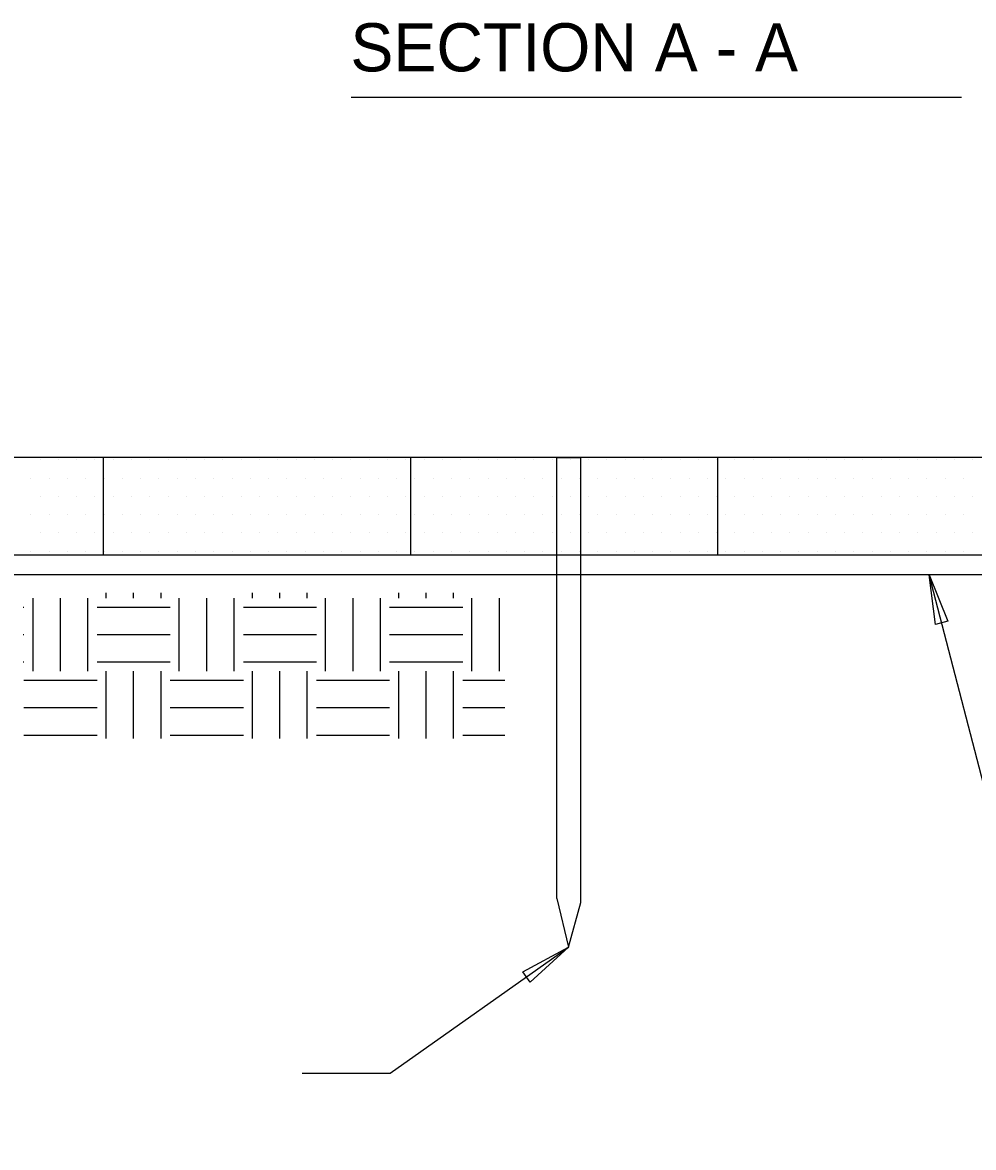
# Model space of a CAD drawing. Extents: x 638850 to 644908, y 297188 to 298900.
# Drawn here: x 641700.1 to 641771.2, y 297633.7 to 297717.8 of the extents above; entities that cross this region are included whole.
import ezdxf

# ---------------------------------------------------------------- set-up
doc = ezdxf.new("R2010")
doc.units = 0
for name, color, linetype in [('11', 7, 'Continuous'), ('12', 7, 'Continuous'), ('3', 7, 'Continuous'), ('4', 7, 'Continuous'), ('5', 7, 'Continuous'), ('6', 7, 'Continuous'), ('7', 7, 'Continuous')]:
    doc.layers.add(name, color=color, linetype=linetype)

msp = doc.modelspace()

# ---------------------------------------------------------------- linework, layer by layer
at = {"layer": '11'}
for p, q in [((641701.416, 297685.127), (641701.416, 297685.127)), ((641702.783, 297685.127), (641702.783, 297685.127)), ((641704.15, 297685.127), (641704.15, 297685.127)), ((641705.517, 297685.127), (641705.517, 297685.127)), ((641706.883, 297685.127), (641706.883, 297685.127)), ((641708.25, 297685.127), (641708.25, 297685.127)), ((641709.617, 297685.127), (641709.617, 297685.127)), ((641710.984, 297685.127), (641710.984, 297685.127)), ((641712.351, 297685.127), (641712.351, 297685.127)), ((641713.718, 297685.127), (641713.718, 297685.127)), ((641715.085, 297685.127), (641715.085, 297685.127)), ((641716.452, 297685.127), (641716.452, 297685.127)), ((641717.818, 297685.127), (641717.818, 297685.127)), ((641719.185, 297685.127), (641719.185, 297685.127)), ((641720.552, 297685.127), (641720.552, 297685.127)), ((641721.919, 297685.127), (641721.919, 297685.127)), ((641723.286, 297685.127), (641723.286, 297685.127)), ((641724.653, 297685.127), (641724.653, 297685.127)), ((641726.02, 297685.127), (641726.02, 297685.127)), ((641727.387, 297685.127), (641727.387, 297685.127)), ((641728.753, 297685.127), (641728.753, 297685.127)), ((641730.12, 297685.127), (641730.12, 297685.127)), ((641731.487, 297685.127), (641731.487, 297685.127)), ((641732.854, 297685.127), (641732.854, 297685.127)), ((641734.221, 297685.127), (641734.221, 297685.127)), ((641735.588, 297685.127), (641735.588, 297685.127)), ((641736.955, 297685.127), (641736.955, 297685.127)), ((641738.322, 297685.127), (641738.322, 297685.127)), ((641739.688, 297685.127), (641739.688, 297685.127)), ((641741.055, 297685.127), (641741.055, 297685.127)), ((641742.422, 297685.127), (641742.422, 297685.127)), ((641743.789, 297685.127), (641743.789, 297685.127)), ((641745.156, 297685.127), (641745.156, 297685.127)), ((641746.523, 297685.127), (641746.523, 297685.127)), ((641747.89, 297685.127), (641747.89, 297685.127)), ((641749.257, 297685.127), (641749.257, 297685.127)), ((641750.623, 297685.127), (641750.623, 297685.127)), ((641751.99, 297685.127), (641751.99, 297685.127)), ((641753.357, 297685.127), (641753.357, 297685.127)), ((641754.724, 297685.127), (641754.724, 297685.127)), ((641756.091, 297685.127), (641756.091, 297685.127)), ((641757.458, 297685.127), (641757.458, 297685.127)), ((641758.825, 297685.127), (641758.825, 297685.127)), ((641760.192, 297685.127), (641760.192, 297685.127)), ((641761.558, 297685.127), (641761.558, 297685.127)), ((641762.925, 297685.127), (641762.925, 297685.127)), ((641764.292, 297685.127), (641764.292, 297685.127)), ((641765.659, 297685.127), (641765.659, 297685.127)), ((641767.026, 297685.127), (641767.026, 297685.127)), ((641768.393, 297685.127), (641768.393, 297685.127)), ((641769.76, 297685.127), (641769.76, 297685.127)), ((641771.127, 297685.127), (641771.127, 297685.127)), ((641700.731, 297683.76), (641700.731, 297683.76)), ((641702.1, 297683.76), (641702.1, 297683.76)), ((641703.465, 297683.76), (641703.465, 297683.76)), ((641704.834, 297683.76), (641704.834, 297683.76)), ((641706.199, 297683.76), (641706.199, 297683.76)), ((641707.568, 297683.76), (641707.568, 297683.76)), ((641708.933, 297683.76), (641708.933, 297683.76)), ((641710.302, 297683.76), (641710.302, 297683.76)), ((641711.666, 297683.76), (641711.666, 297683.76)), ((641713.035, 297683.76), (641713.035, 297683.76)), ((641714.4, 297683.76), (641714.4, 297683.76)), ((641715.769, 297683.76), (641715.769, 297683.76)), ((641717.134, 297683.76), (641717.134, 297683.76)), ((641718.503, 297683.76), (641718.503, 297683.76)), ((641719.868, 297683.76), (641719.868, 297683.76)), ((641721.237, 297683.76), (641721.237, 297683.76)), ((641722.601, 297683.76), (641722.601, 297683.76)), ((641723.97, 297683.76), (641723.97, 297683.76)), ((641725.335, 297683.76), (641725.335, 297683.76)), ((641726.704, 297683.76), (641726.704, 297683.76)), ((641728.069, 297683.76), (641728.069, 297683.76)), ((641729.438, 297683.76), (641729.438, 297683.76)), ((641730.803, 297683.76), (641730.803, 297683.76)), ((641732.172, 297683.76), (641732.172, 297683.76)), ((641733.536, 297683.76), (641733.536, 297683.76)), ((641734.905, 297683.76), (641734.905, 297683.76)), ((641736.27, 297683.76), (641736.27, 297683.76)), ((641737.639, 297683.76), (641737.639, 297683.76)), ((641739.004, 297683.76), (641739.004, 297683.76)), ((641740.373, 297683.76), (641740.373, 297683.76)), ((641741.738, 297683.76), (641741.738, 297683.76)), ((641743.107, 297683.76), (641743.107, 297683.76)), ((641744.471, 297683.76), (641744.471, 297683.76)), ((641745.84, 297683.76), (641745.84, 297683.76)), ((641747.205, 297683.76), (641747.205, 297683.76)), ((641748.574, 297683.76), (641748.574, 297683.76)), ((641749.939, 297683.76), (641749.939, 297683.76)), ((641751.308, 297683.76), (641751.308, 297683.76)), ((641752.673, 297683.76), (641752.673, 297683.76)), ((641754.042, 297683.76), (641754.042, 297683.76)), ((641755.406, 297683.76), (641755.406, 297683.76)), ((641756.775, 297683.76), (641756.775, 297683.76)), ((641758.14, 297683.76), (641758.14, 297683.76)), ((641759.509, 297683.76), (641759.509, 297683.76)), ((641760.874, 297683.76), (641760.874, 297683.76)), ((641762.243, 297683.76), (641762.243, 297683.76)), ((641763.608, 297683.76), (641763.608, 297683.76)), ((641764.977, 297683.76), (641764.977, 297683.76)), ((641766.341, 297683.76), (641766.341, 297683.76)), ((641767.71, 297683.76), (641767.71, 297683.76)), ((641769.075, 297683.76), (641769.075, 297683.76)), ((641770.444, 297683.76), (641770.444, 297683.76)), ((641701.416, 297682.393), (641701.416, 297682.393)), ((641702.783, 297682.393), (641702.783, 297682.393)), ((641704.15, 297682.393), (641704.15, 297682.393)), ((641705.517, 297682.393), (641705.517, 297682.393)), ((641706.883, 297682.393), (641706.883, 297682.393)), ((641708.25, 297682.393), (641708.25, 297682.393)), ((641709.617, 297682.393), (641709.617, 297682.393)), ((641710.984, 297682.393), (641710.984, 297682.393)), ((641712.351, 297682.393), (641712.351, 297682.393)), ((641713.718, 297682.393), (641713.718, 297682.393)), ((641715.085, 297682.393), (641715.085, 297682.393)), ((641716.452, 297682.393), (641716.452, 297682.393)), ((641717.818, 297682.393), (641717.818, 297682.393)), ((641719.185, 297682.393), (641719.185, 297682.393)), ((641720.552, 297682.393), (641720.552, 297682.393)), ((641721.919, 297682.393), (641721.919, 297682.393)), ((641723.286, 297682.393), (641723.286, 297682.393)), ((641724.653, 297682.393), (641724.653, 297682.393)), ((641726.02, 297682.393), (641726.02, 297682.393)), ((641727.387, 297682.393), (641727.387, 297682.393)), ((641728.753, 297682.393), (641728.753, 297682.393)), ((641730.12, 297682.393), (641730.12, 297682.393)), ((641731.487, 297682.393), (641731.487, 297682.393)), ((641732.854, 297682.393), (641732.854, 297682.393)), ((641734.221, 297682.393), (641734.221, 297682.393)), ((641735.588, 297682.393), (641735.588, 297682.393)), ((641736.955, 297682.393), (641736.955, 297682.393)), ((641738.322, 297682.393), (641738.322, 297682.393)), ((641739.688, 297682.393), (641739.688, 297682.393)), ((641741.055, 297682.393), (641741.055, 297682.393)), ((641742.422, 297682.393), (641742.422, 297682.393)), ((641743.789, 297682.393), (641743.789, 297682.393)), ((641745.156, 297682.393), (641745.156, 297682.393)), ((641746.523, 297682.393), (641746.523, 297682.393)), ((641747.89, 297682.393), (641747.89, 297682.393)), ((641749.257, 297682.393), (641749.257, 297682.393)), ((641750.623, 297682.393), (641750.623, 297682.393)), ((641751.99, 297682.393), (641751.99, 297682.393)), ((641753.357, 297682.393), (641753.357, 297682.393)), ((641754.724, 297682.393), (641754.724, 297682.393)), ((641756.091, 297682.393), (641756.091, 297682.393)), ((641757.458, 297682.393), (641757.458, 297682.393)), ((641758.825, 297682.393), (641758.825, 297682.393)), ((641760.192, 297682.393), (641760.192, 297682.393)), ((641761.558, 297682.393), (641761.558, 297682.393)), ((641762.925, 297682.393), (641762.925, 297682.393)), ((641764.292, 297682.393), (641764.292, 297682.393)), ((641765.659, 297682.393), (641765.659, 297682.393)), ((641767.026, 297682.393), (641767.026, 297682.393)), ((641768.393, 297682.393), (641768.393, 297682.393)), ((641769.76, 297682.393), (641769.76, 297682.393)), ((641771.127, 297682.393), (641771.127, 297682.393)), ((641700.731, 297681.026), (641700.731, 297681.026)), ((641702.1, 297681.026), (641702.1, 297681.026)), ((641703.465, 297681.026), (641703.465, 297681.026)), ((641704.834, 297681.026), (641704.834, 297681.026)), ((641706.199, 297681.026), (641706.199, 297681.026)), ((641707.568, 297681.026), (641707.568, 297681.026)), ((641708.933, 297681.026), (641708.933, 297681.026)), ((641710.302, 297681.026), (641710.302, 297681.026)), ((641711.666, 297681.026), (641711.666, 297681.026)), ((641713.035, 297681.026), (641713.035, 297681.026)), ((641714.4, 297681.026), (641714.4, 297681.026)), ((641715.769, 297681.026), (641715.769, 297681.026)), ((641717.134, 297681.026), (641717.134, 297681.026)), ((641718.503, 297681.026), (641718.503, 297681.026)), ((641719.868, 297681.026), (641719.868, 297681.026)), ((641721.237, 297681.026), (641721.237, 297681.026)), ((641722.601, 297681.026), (641722.601, 297681.026)), ((641723.97, 297681.026), (641723.97, 297681.026)), ((641725.335, 297681.026), (641725.335, 297681.026)), ((641726.704, 297681.026), (641726.704, 297681.026)), ((641728.069, 297681.026), (641728.069, 297681.026)), ((641729.438, 297681.026), (641729.438, 297681.026)), ((641730.803, 297681.026), (641730.803, 297681.026)), ((641732.172, 297681.026), (641732.172, 297681.026)), ((641733.536, 297681.026), (641733.536, 297681.026)), ((641734.905, 297681.026), (641734.905, 297681.026)), ((641736.27, 297681.026), (641736.27, 297681.026)), ((641737.639, 297681.026), (641737.639, 297681.026)), ((641739.004, 297681.026), (641739.004, 297681.026)), ((641740.373, 297681.026), (641740.373, 297681.026)), ((641741.738, 297681.026), (641741.738, 297681.026)), ((641743.107, 297681.026), (641743.107, 297681.026)), ((641744.471, 297681.026), (641744.471, 297681.026)), ((641745.84, 297681.026), (641745.84, 297681.026)), ((641747.205, 297681.026), (641747.205, 297681.026)), ((641748.574, 297681.026), (641748.574, 297681.026)), ((641749.939, 297681.026), (641749.939, 297681.026)), ((641751.308, 297681.026), (641751.308, 297681.026)), ((641752.673, 297681.026), (641752.673, 297681.026)), ((641754.042, 297681.026), (641754.042, 297681.026)), ((641755.406, 297681.026), (641755.406, 297681.026)), ((641756.775, 297681.026), (641756.775, 297681.026)), ((641758.14, 297681.026), (641758.14, 297681.026)), ((641759.509, 297681.026), (641759.509, 297681.026)), ((641760.874, 297681.026), (641760.874, 297681.026)), ((641762.243, 297681.026), (641762.243, 297681.026)), ((641763.608, 297681.026), (641763.608, 297681.026)), ((641764.977, 297681.026), (641764.977, 297681.026)), ((641766.341, 297681.026), (641766.341, 297681.026)), ((641767.71, 297681.026), (641767.71, 297681.026)), ((641769.075, 297681.026), (641769.075, 297681.026)), ((641770.444, 297681.026), (641770.444, 297681.026)), ((641701.416, 297679.659), (641701.416, 297679.659)), ((641702.783, 297679.659), (641702.783, 297679.659)), ((641704.15, 297679.659), (641704.15, 297679.659)), ((641705.517, 297679.659), (641705.517, 297679.659)), ((641706.883, 297679.659), (641706.883, 297679.659)), ((641708.25, 297679.659), (641708.25, 297679.659)), ((641709.617, 297679.659), (641709.617, 297679.659)), ((641710.984, 297679.659), (641710.984, 297679.659)), ((641712.351, 297679.659), (641712.351, 297679.659)), ((641713.718, 297679.659), (641713.718, 297679.659)), ((641715.085, 297679.659), (641715.085, 297679.659)), ((641716.452, 297679.659), (641716.452, 297679.659)), ((641717.818, 297679.659), (641717.818, 297679.659)), ((641719.185, 297679.659), (641719.185, 297679.659)), ((641720.552, 297679.659), (641720.552, 297679.659)), ((641721.919, 297679.659), (641721.919, 297679.659)), ((641723.286, 297679.659), (641723.286, 297679.659)), ((641724.653, 297679.659), (641724.653, 297679.659)), ((641726.02, 297679.659), (641726.02, 297679.659)), ((641727.387, 297679.659), (641727.387, 297679.659)), ((641728.753, 297679.659), (641728.753, 297679.659)), ((641730.12, 297679.659), (641730.12, 297679.659)), ((641731.487, 297679.659), (641731.487, 297679.659)), ((641732.854, 297679.659), (641732.854, 297679.659)), ((641734.221, 297679.659), (641734.221, 297679.659)), ((641735.588, 297679.659), (641735.588, 297679.659)), ((641736.955, 297679.659), (641736.955, 297679.659)), ((641738.322, 297679.659), (641738.322, 297679.659)), ((641739.688, 297679.659), (641739.688, 297679.659)), ((641741.055, 297679.659), (641741.055, 297679.659)), ((641742.422, 297679.659), (641742.422, 297679.659)), ((641743.789, 297679.659), (641743.789, 297679.659)), ((641745.156, 297679.659), (641745.156, 297679.659)), ((641746.523, 297679.659), (641746.523, 297679.659)), ((641747.89, 297679.659), (641747.89, 297679.659)), ((641749.257, 297679.659), (641749.257, 297679.659)), ((641750.623, 297679.659), (641750.623, 297679.659)), ((641751.99, 297679.659), (641751.99, 297679.659)), ((641753.357, 297679.659), (641753.357, 297679.659)), ((641754.724, 297679.659), (641754.724, 297679.659)), ((641756.091, 297679.659), (641756.091, 297679.659)), ((641757.458, 297679.659), (641757.458, 297679.659)), ((641758.825, 297679.659), (641758.825, 297679.659)), ((641760.192, 297679.659), (641760.192, 297679.659)), ((641761.558, 297679.659), (641761.558, 297679.659)), ((641762.925, 297679.659), (641762.925, 297679.659)), ((641764.292, 297679.659), (641764.292, 297679.659)), ((641765.659, 297679.659), (641765.659, 297679.659)), ((641767.026, 297679.659), (641767.026, 297679.659)), ((641768.393, 297679.659), (641768.393, 297679.659)), ((641769.76, 297679.659), (641769.76, 297679.659)), ((641771.127, 297679.659), (641771.127, 297679.659)), ((641700.731, 297678.292), (641700.731, 297678.292)), ((641702.1, 297678.292), (641702.1, 297678.292)), ((641703.465, 297678.292), (641703.465, 297678.292)), ((641704.834, 297678.292), (641704.834, 297678.292)), ((641706.199, 297678.292), (641706.199, 297678.292)), ((641707.568, 297678.292), (641707.568, 297678.292)), ((641708.933, 297678.292), (641708.933, 297678.292)), ((641710.302, 297678.292), (641710.302, 297678.292)), ((641711.666, 297678.292), (641711.666, 297678.292)), ((641713.035, 297678.292), (641713.035, 297678.292)), ((641714.4, 297678.292), (641714.4, 297678.292)), ((641715.769, 297678.292), (641715.769, 297678.292)), ((641717.134, 297678.292), (641717.134, 297678.292)), ((641718.503, 297678.292), (641718.503, 297678.292)), ((641719.868, 297678.292), (641719.868, 297678.292)), ((641721.237, 297678.292), (641721.237, 297678.292)), ((641722.601, 297678.292), (641722.601, 297678.292)), ((641723.97, 297678.292), (641723.97, 297678.292)), ((641725.335, 297678.292), (641725.335, 297678.292)), ((641726.704, 297678.292), (641726.704, 297678.292)), ((641728.069, 297678.292), (641728.069, 297678.292)), ((641729.438, 297678.292), (641729.438, 297678.292)), ((641730.803, 297678.292), (641730.803, 297678.292)), ((641732.172, 297678.292), (641732.172, 297678.292)), ((641733.536, 297678.292), (641733.536, 297678.292)), ((641734.905, 297678.292), (641734.905, 297678.292)), ((641736.27, 297678.292), (641736.27, 297678.292)), ((641737.639, 297678.292), (641737.639, 297678.292)), ((641739.004, 297678.292), (641739.004, 297678.292)), ((641740.373, 297678.292), (641740.373, 297678.292)), ((641741.738, 297678.292), (641741.738, 297678.292)), ((641743.107, 297678.292), (641743.107, 297678.292)), ((641744.471, 297678.292), (641744.471, 297678.292)), ((641745.84, 297678.292), (641745.84, 297678.292)), ((641747.205, 297678.292), (641747.205, 297678.292)), ((641748.574, 297678.292), (641748.574, 297678.292)), ((641749.939, 297678.292), (641749.939, 297678.292)), ((641751.308, 297678.292), (641751.308, 297678.292)), ((641752.673, 297678.292), (641752.673, 297678.292)), ((641754.042, 297678.292), (641754.042, 297678.292)), ((641755.406, 297678.292), (641755.406, 297678.292)), ((641756.775, 297678.292), (641756.775, 297678.292)), ((641758.14, 297678.292), (641758.14, 297678.292)), ((641759.509, 297678.292), (641759.509, 297678.292)), ((641760.874, 297678.292), (641760.874, 297678.292)), ((641762.243, 297678.292), (641762.243, 297678.292)), ((641763.608, 297678.292), (641763.608, 297678.292)), ((641764.977, 297678.292), (641764.977, 297678.292)), ((641766.341, 297678.292), (641766.341, 297678.292)), ((641767.71, 297678.292), (641767.71, 297678.292)), ((641769.075, 297678.292), (641769.075, 297678.292)), ((641770.444, 297678.292), (641770.444, 297678.292))]:
    msp.add_line(p, q, dxfattribs=at)
at = {"layer": '12'}
for p, q in [((641706.361, 297674.786), (641706.361, 297675.163)), ((641708.412, 297674.786), (641708.412, 297675.163)), ((641710.461, 297674.786), (641710.461, 297675.163)), ((641717.296, 297674.786), (641717.296, 297675.163)), ((641719.347, 297674.786), (641719.347, 297675.163)), ((641721.396, 297674.786), (641721.396, 297675.163)), ((641728.231, 297674.786), (641728.231, 297675.163)), ((641730.282, 297674.786), (641730.282, 297675.163)), ((641732.331, 297674.786), (641732.331, 297675.163)), ((641700.893, 297669.319), (641700.893, 297674.786)), ((641702.945, 297669.319), (641702.945, 297674.786)), ((641704.994, 297669.319), (641704.994, 297674.786)), ((641711.828, 297669.319), (641711.828, 297674.786)), ((641713.88, 297669.319), (641713.88, 297674.786)), ((641715.929, 297669.319), (641715.929, 297674.786)), ((641722.763, 297669.319), (641722.763, 297674.786)), ((641724.815, 297669.319), (641724.815, 297674.786)), ((641726.864, 297669.319), (641726.864, 297674.786)), ((641733.698, 297669.319), (641733.698, 297674.786)), ((641735.75, 297669.319), (641735.75, 297674.786)), ((641700.163, 297674.104), (641700.211, 297674.104)), ((641705.678, 297674.104), (641711.146, 297674.104)), ((641716.613, 297674.104), (641722.081, 297674.104)), ((641727.548, 297674.104), (641733.016, 297674.104)), ((641700.163, 297672.053), (641700.211, 297672.053)), ((641705.678, 297672.053), (641711.146, 297672.053)), ((641716.613, 297672.053), (641722.081, 297672.053)), ((641727.548, 297672.053), (641733.016, 297672.053)), ((641700.163, 297670.003), (641700.211, 297670.003)), ((641705.678, 297670.003), (641711.146, 297670.003)), ((641706.361, 297664.271), (641706.361, 297669.319)), ((641708.412, 297664.271), (641708.412, 297669.319)), ((641710.461, 297664.271), (641710.461, 297669.319)), ((641716.613, 297670.003), (641722.081, 297670.003)), ((641717.296, 297664.271), (641717.296, 297669.319)), ((641719.347, 297664.271), (641719.347, 297669.319)), ((641721.396, 297664.271), (641721.396, 297669.319)), ((641727.548, 297670.003), (641733.016, 297670.003)), ((641728.231, 297664.271), (641728.231, 297669.319)), ((641730.282, 297664.271), (641730.282, 297669.319)), ((641732.331, 297664.271), (641732.331, 297669.319)), ((641700.211, 297668.637), (641705.678, 297668.637)), ((641711.146, 297668.637), (641716.613, 297668.637)), ((641722.081, 297668.637), (641727.548, 297668.637)), ((641733.016, 297668.637), (641736.165, 297668.637)), ((641700.211, 297666.585), (641705.678, 297666.585)), ((641711.146, 297666.585), (641716.613, 297666.585)), ((641722.081, 297666.585), (641727.548, 297666.585)), ((641733.016, 297666.585), (641736.165, 297666.585)), ((641700.211, 297664.536), (641705.678, 297664.536)), ((641711.146, 297664.536), (641716.613, 297664.536)), ((641722.081, 297664.536), (641727.548, 297664.536)), ((641733.016, 297664.536), (641736.165, 297664.536))]:
    msp.add_line(p, q, dxfattribs=at)
at = {"layer": '3'}
msp.add_line((641724.678, 297712.248), (641770.302, 297712.248), dxfattribs=at)
at = {"layer": '4'}
for p, q in [((641660.237, 297685.317), (641843.945, 297685.317)), ((641706.164, 297678.028), (641706.164, 297685.317)), ((641729.127, 297678.028), (641729.127, 297685.317)), ((641752.091, 297678.028), (641752.091, 297685.317)), ((641660.237, 297678.028), (641843.945, 297678.028))]:
    msp.add_line(p, q, dxfattribs=at)
at = {"layer": '5'}
for p, q in [((641778.971, 297633.684), (641767.892, 297676.521)), ((641727.592, 297639.254), (641740.918, 297648.667)), ((641721.014, 297639.254), (641727.592, 297639.254))]:
    msp.add_line(p, q, dxfattribs=at)
for points in [[(641768.364, 297672.807), (641767.892, 297676.521), (641769.279, 297673.043)], [(641737.499, 297646.83), (641740.918, 297648.667), (641738.044, 297646.06)]]:
    msp.add_lwpolyline(points, close=True, dxfattribs=at)
at = {"layer": '6'}
for p, q in [((641740.054, 297652.315), (641740.054, 297685.308)), ((641740.054, 297685.308), (641741.845, 297685.308)), ((641741.845, 297652.002), (641741.845, 297685.308)), ((641740.054, 297652.315), (641740.926, 297648.658)), ((641740.926, 297648.658), (641741.845, 297652.002))]:
    msp.add_line(p, q, dxfattribs=at)
at = {"layer": '7'}
msp.add_line((641660.237, 297676.545), (641843.945, 297676.545), dxfattribs=at)

# ---------------------------------------------------------------- texts
at = {"layer": '3'}
msp.add_text('SECTION A - A', height=3.60225, dxfattribs=at).set_placement((641724.619, 297714.18))

doc.saveas('drawing.dxf')
